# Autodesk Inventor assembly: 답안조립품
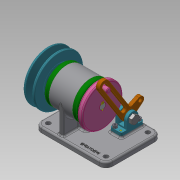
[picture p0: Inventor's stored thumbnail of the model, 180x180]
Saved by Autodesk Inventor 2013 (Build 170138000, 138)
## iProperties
Created: 2019-09
Part Number: 답안조립품
Document SubType Name: Assembly
Designer: Administrator
Mass: 1417.86 g
Surface Area: 1426.65 cm^2
Volume: 427.118 cm^3
Density: 3.31959 g/cm^3
Author: Administrator
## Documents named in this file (19)
- C:\Users\Administrator\Desktop\390904V1010\답안조립품.iam
- C:\Users\Administrator\Desktop\390904V1010\본체.ipt
- C:\Users\Administrator\Desktop\390904V1010\V-벨트풀리.ipt
- C:\Users\Administrator\Desktop\390904V1010\너트 M8.ipt
- C:\Users\Administrator\Desktop\390904V1010\너트 M10x1.ipt
- C:\Users\Administrator\Desktop\390904V1010\돌림판.ipt
- C:\Users\Administrator\Desktop\390904V1010\멈춤나사 M3x5.ipt
- C:\Users\Administrator\Desktop\390904V1010\베어링 6004.ipt
- C:\Users\Administrator\Desktop\390904V1010\볼트 M4.ipt
- C:\Users\Administrator\Desktop\390904V1010\오일 실 17 30 5.ipt
- C:\Users\Administrator\Desktop\390904V1010\와셔 8x15.5.ipt
- C:\Users\Administrator\Desktop\390904V1010\축.ipt
- C:\Users\Administrator\Desktop\390904V1010\커버.ipt
- C:\Users\Administrator\Desktop\390904V1010\크랭크.ipt
- C:\Users\Administrator\Desktop\390904V1010\키 4 x 4 x 8.ipt
- C:\Users\Administrator\Desktop\390904V1010\키 5 x 5 x 12.ipt
- C:\Users\Administrator\Desktop\390904V1010\핀 3 x 8.ipt
- C:\Users\Administrator\Desktop\390904V1010\힌지 축.ipt
- C:\Users\Administrator\Desktop\390904V1010\힌지.ipt
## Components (3 placed, 2 different names)
1. V-벨트풀리:1
2. 핀 3 x 8:1 — 플러쉬:1
3. 핀 3 x 8:2 — 플러쉬:2
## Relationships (2: Flush 2)
- 플러쉬:1 [Flush]: 핀 3 x 8:1
- 플러쉬:2 [Flush]: 핀 3 x 8:2
